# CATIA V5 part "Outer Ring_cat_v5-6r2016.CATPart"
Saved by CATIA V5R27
Part number: Outer Ring
Bounding box of the stored display mesh (mm): x -99.995 to 99.995, y 0 to 50, z -99.998 to 99.998
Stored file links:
  E:\_Deepak\2017_Deepak\CATIA\Resources\Tutorial Files\Tutorials\c16_catia_v5_6r2016_tut\Bearing\Outer Ring_cat_v5-6r2016.CATPart
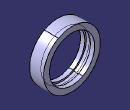
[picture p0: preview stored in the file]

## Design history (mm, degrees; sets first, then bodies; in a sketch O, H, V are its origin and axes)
Body1 (main body)
  Sketch1 on yz-plane, origin (0, 0, 0), H (0, 1, 0), V (0, 0, 1)
    point P1 (0, 80)
    line L1 (0, 80) -> (0, 100)
    line L2 (0, 100) -> (50, 100)
    line L3 (50, 100) -> (50, 80)
    line L4 (50, 80) -> (35, 80)
    line L5 (35, 80) -> (35, 85)
    line L6 (35, 85) -> (15, 85)
    line L7 (15, 85) -> (15, 80)
    point P8 (15, 80)
    line L8 (15, 80) -> (0, 80)
    point P9 (0, 80)
    distance H L8 = 80
    length L2 = 50
    length L5 = 5
    length L8 = 15
    length L4 = 15
    length L1 = 20
    coincidence: P1 V, P8 L4, P9 V, P9 P1
    vertical: L1 V, L3 V, L5 V, L7 V
    horizontal: L2 H, L4 H, L6 H, L8 H
  Shaft1: profile Sketch1, axis Sketch1.H, angle 360
  Plane1: type Offset, RefPlane face of Shaft1 from Sketch1.L5, Offset 10, reversed
  Sketch2 on Plane1, origin (0, 25, 0), H (-1, 0, 0), V (0, 0, 1)
    projected circle E1 centre (0, 0) radius 85 from edge [face of Shaft1 from Sketch1.L6 | face of Shaft1 from Sketch1.L7]
  Point1: type OnCurve, Support Sketch2, RefPoint {extremum Reference Sketch2, Direction (1, 2, 3)}, Length 282.187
